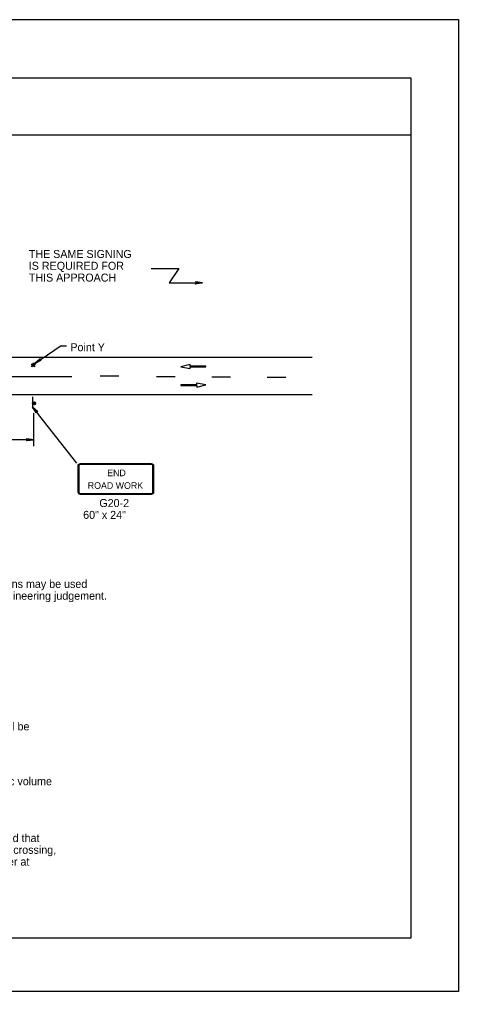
# Model space of a CAD drawing. Extents: x -14145 to -13662, y 30244 to 30661.
# Drawn here: x -13870.69 to -13859.17, y 30343.81 to 30369.31 of the extents above; entities that cross this region are included whole.
import ezdxf

# ---------------------------------------------------------------- set-up
doc = ezdxf.new("R2010")
doc.units = 0
for name, color, linetype in [('1', 7, 'Continuous'), ('10', 7, 'Continuous'), ('2', 7, 'Continuous'), ('61', 7, 'Continuous')]:
    doc.layers.add(name, color=color, linetype=linetype)

msp = doc.modelspace()

# ---------------------------------------------------------------- linework, layer by layer
at = {"layer": '1'}
for p, q in [((-13867.233, 30362.772), (-13866.507, 30362.772)), ((-13866.507, 30362.773), (-13866.759, 30362.4)), ((-13866.759, 30362.4), (-13865.888, 30362.4)), ((-13870.282, 30360.286), (-13869.622, 30360.739)), ((-13869.457, 30360.739), (-13869.622, 30360.739)), ((-13889.291, 30360.451), (-13863.011, 30360.451)), ((-13870.352, 30360.237), (-13870.364, 30360.195)), ((-13866.216, 30360.259), (-13866.458, 30360.193)), ((-13866.458, 30360.193), (-13866.214, 30360.147)), ((-13866.216, 30360.214), (-13866.216, 30360.259)), ((-13865.8, 30360.214), (-13866.216, 30360.214)), ((-13866.214, 30360.147), (-13866.214, 30360.192)), ((-13866.214, 30360.192), (-13865.8, 30360.192)), ((-13865.8, 30360.192), (-13865.8, 30360.214)), ((-13873.509, 30359.944), (-13869.316, 30359.944)), ((-13868.083, 30359.953), (-13868.569, 30359.953)), ((-13866.607, 30359.929), (-13867.093, 30359.929)), ((-13865.155, 30359.923), (-13865.641, 30359.923)), ((-13863.703, 30359.917), (-13864.189, 30359.917)), ((-13866.044, 30359.724), (-13866.458, 30359.724)), ((-13866.458, 30359.724), (-13866.458, 30359.702)), ((-13866.458, 30359.702), (-13866.041, 30359.702)), ((-13865.8, 30359.723), (-13866.044, 30359.769)), ((-13866.044, 30359.769), (-13866.044, 30359.724)), ((-13866.041, 30359.657), (-13865.8, 30359.723)), ((-13866.041, 30359.702), (-13866.041, 30359.657)), ((-13889.291, 30359.467), (-13863.011, 30359.467)), ((-13870.345, 30359.409), (-13870.345, 30359.097)), ((-13869.184, 30357.665), (-13870.345, 30359.147)), ((-13870.315, 30358.114), (-13870.315, 30358.978)), ((-13870.315, 30358.283), (-13872.775, 30358.283)), ((-13869.159, 30357.598), (-13869.159, 30356.91)), ((-13869.134, 30357.598), (-13869.134, 30356.91)), ((-13867.225, 30357.649), (-13869.098, 30357.649)), ((-13867.225, 30357.649), (-13869.098, 30357.649)), ((-13867.225, 30357.634), (-13869.098, 30357.634)), ((-13867.225, 30357.634), (-13869.098, 30357.634)), ((-13867.189, 30356.91), (-13867.189, 30357.598)), ((-13867.164, 30356.91), (-13867.164, 30357.598)), ((-13869.098, 30356.873), (-13867.225, 30356.873)), ((-13869.098, 30356.858), (-13867.225, 30356.858))]:
    msp.add_line(p, q, dxfattribs=at)
for points in [[(-13866.067, 30362.421), (-13866.059, 30362.407), (-13865.887, 30362.399), (-13866.067, 30362.421), (-13866.072, 30362.428), (-13865.887, 30362.399), (-13866.058, 30362.387), (-13866.066, 30362.377), (-13865.887, 30362.399), (-13866.075, 30362.367), (-13866.066, 30362.377)], [(-13870.145, 30360.404), (-13870.15, 30360.391), (-13870.282, 30360.286), (-13870.145, 30360.404), (-13870.142, 30360.417), (-13870.282, 30360.286), (-13870.134, 30360.376), (-13870.126, 30360.365), (-13870.282, 30360.286), (-13870.115, 30360.368), (-13870.126, 30360.365)], [(-13870.251, 30358.992), (-13870.245, 30359.007), (-13870.345, 30359.147), (-13870.251, 30358.992), (-13870.254, 30358.984), (-13870.345, 30359.147), (-13870.23, 30359.02), (-13870.217, 30359.02), (-13870.345, 30359.147), (-13870.204, 30359.019), (-13870.217, 30359.02)], [(-13870.495, 30358.307), (-13870.489, 30358.289), (-13870.315, 30358.283), (-13870.495, 30358.307), (-13870.501, 30358.313), (-13870.315, 30358.283), (-13870.489, 30358.277), (-13870.495, 30358.259), (-13870.315, 30358.283), (-13870.501, 30358.253), (-13870.495, 30358.259)]]:
    msp.add_lwpolyline(points, dxfattribs=at)
msp.add_circle((-13870.305, 30359.238), 0.0408, dxfattribs=at)
msp.add_arc((-13870.31, 30359.245), 0.0214, 189.521, 184.2501, dxfattribs=at)
for centre, major_axis, ratio, start_param, end_param in [((-13869.097, 30357.597), (0.0609, 0), 0.839899, 1.570796, 3.141593), ((-13869.097, 30357.597), (0, -0.0365), 0.999938, 3.141593, 4.712389), ((-13867.224, 30357.597), (-0.0609, 0), 0.839899, 3.141593, 4.712389), ((-13867.224, 30357.597), (0, 0.0365), 0.999938, 4.712389, 6.283185), ((-13869.097, 30356.909), (0.0609, 0), 0.839899, 3.141593, 4.712389), ((-13869.097, 30356.909), (0, -0.0365), 0.999938, 4.712389, 6.283185), ((-13867.224, 30356.909), (0, 0.0365), 0.999938, 3.141593, 4.712389), ((-13867.224, 30356.909), (-0.0609, 0), 0.839899, 1.570796, 3.141593)]:
    msp.add_ellipse(centre, major_axis=major_axis, ratio=ratio, start_param=start_param, end_param=end_param, dxfattribs=at)
at = {"layer": '10'}
for p, q in [((-13891.874, 30367.777), (-13860.422, 30367.777)), ((-13860.422, 30367.777), (-13860.422, 30345.207)), ((-13891.874, 30366.277), (-13860.422, 30366.277)), ((-13860.422, 30345.207), (-13891.874, 30345.207))]:
    msp.add_line(p, q, dxfattribs=at)
at = {"layer": '2'}
for p, q in [((-13870.34, 30360.261), (-13870.322, 30360.303)), ((-13870.322, 30360.303), (-13870.31, 30360.261)), ((-13870.352, 30360.237), (-13870.382, 30360.261)), ((-13870.382, 30360.261), (-13870.34, 30360.261)), ((-13870.364, 30360.195), (-13870.352, 30360.237)), ((-13870.328, 30360.225), (-13870.364, 30360.195)), ((-13870.298, 30360.195), (-13870.328, 30360.225)), ((-13870.31, 30360.261), (-13870.268, 30360.261)), ((-13870.268, 30360.261), (-13870.304, 30360.237)), ((-13870.304, 30360.237), (-13870.298, 30360.195))]:
    msp.add_line(p, q, dxfattribs=at)
msp.add_lwpolyline([(-13870.328, 30360.285), (-13870.334, 30360.255), (-13870.37, 30360.255), (-13870.346, 30360.243), (-13870.358, 30360.207), (-13870.328, 30360.225), (-13870.298, 30360.207), (-13870.31, 30360.243), (-13870.28, 30360.255), (-13870.316, 30360.255), (-13870.322, 30360.291), (-13870.328, 30360.249), (-13870.358, 30360.255), (-13870.34, 30360.243), (-13870.352, 30360.213), (-13870.328, 30360.231), (-13870.304, 30360.213), (-13870.316, 30360.243), (-13870.292, 30360.255), (-13870.316, 30360.255), (-13870.322, 30360.273), (-13870.328, 30360.249), (-13870.346, 30360.249), (-13870.334, 30360.243), (-13870.34, 30360.225), (-13870.328, 30360.237), (-13870.316, 30360.225), (-13870.316, 30360.243), (-13870.298, 30360.249), (-13870.316, 30360.249), (-13870.322, 30360.255), (-13870.322, 30360.243), (-13870.334, 30360.243), (-13870.334, 30360.243), (-13870.334, 30360.231), (-13870.328, 30360.237), (-13870.316, 30360.231), (-13870.322, 30360.243), (-13870.31, 30360.243), (-13870.322, 30360.243), (-13870.322, 30360.243), (-13870.328, 30360.243), (-13870.328, 30360.243), (-13870.322, 30360.237), (-13870.328, 30360.243), (-13870.328, 30360.243), (-13870.328, 30360.243), (-13870.328, 30360.243)], dxfattribs=at)
at = {"layer": '61'}
msp.add_lwpolyline([(-13892.174, 30369.307), (-13859.174, 30369.307), (-13859.174, 30343.807), (-13892.174, 30343.807)], close=True, dxfattribs=at)

# ---------------------------------------------------------------- texts
at = {"layer": '1'}
for s, p in [('END', (-13868.388, 30357.325)), ('ROAD WORK', (-13868.897, 30356.994))]:
    msp.add_text(s, height=0.173, dxfattribs=at).set_placement(p)
at = {"layer": '2'}
for s, p in [('THE SAME SIGNING', (-13870.444, 30363.05)), ('IS REQUIRED FOR', (-13870.444, 30362.74)), ('THIS APPROACH', (-13870.444, 30362.43)), ('Point Y', (-13869.353, 30360.604)), ('G20-2', (-13868.594, 30356.516)), ('60" x 24"', (-13869.018, 30356.206)), ('Additional signs may be used', (-13872.563, 30354.395)), ('based on engineering judgement.', (-13872.563, 30354.085)), ('    a. Sight distance between the flagger and any vehicle between Points X and Y will be', (-13881.324, 30350.658)), ('    c. The ADT is not greater than approximately 1500, or the average 5-minute traffic volume', (-13881.324, 30349.219)), ('4.  When a highway-rail grade crossing exists within the work zone, or it is anticipated that', (-13881.324, 30347.73)), ('    queues resulting from the lane closure might extend through a highway-rail grade crossing,', (-13881.324, 30347.42)), ('    provisions shall be made to eliminate conflicts, which may require placing a flagger at', (-13881.324, 30347.11))]:
    msp.add_text(s, height=0.21, dxfattribs=at).set_placement(p)

doc.saveas('drawing.dxf')
